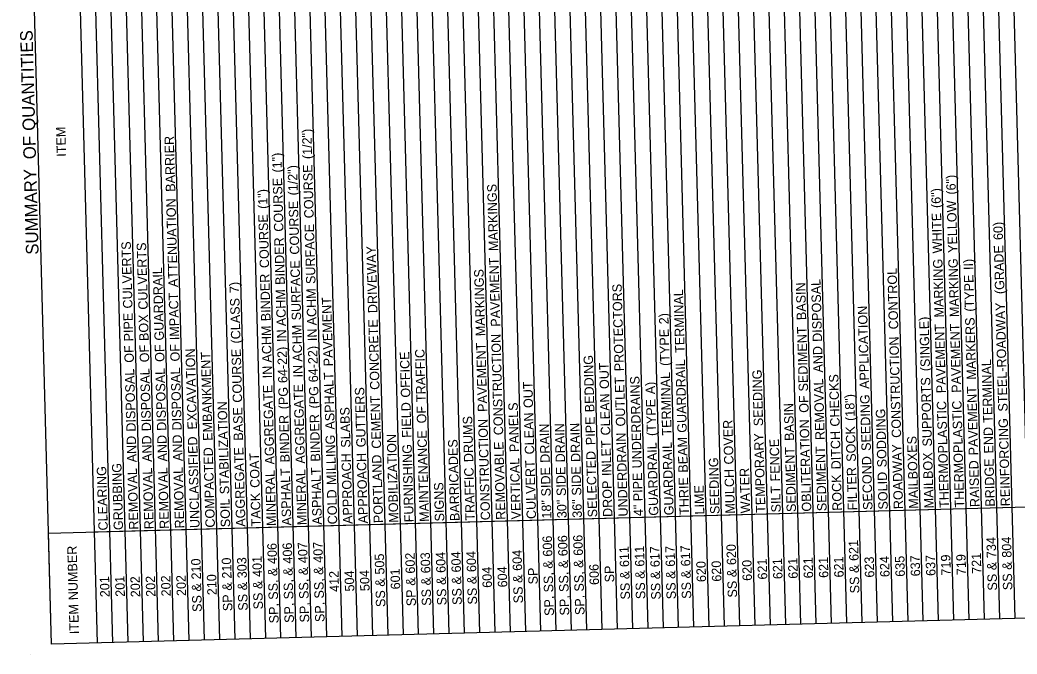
# Model space of a CAD drawing. Extents: x 1930078 to 1931323, y 596452 to 607874.
# Drawn here: x 1930078 to 1930714, y 606741 to 607145 of the extents above; entities that cross this region are included whole.
import ezdxf

# ---------------------------------------------------------------- set-up
doc = ezdxf.new("R2010")
doc.units = 0
doc.layers.add('Default', color=7, linetype='Continuous')
doc.layers.add('R_Border', color=7, linetype='Continuous')

msp = doc.modelspace()

# ---------------------------------------------------------------- linework, layer by layer
at = {"layer": 'Default'}
for p, q in [((1930546.92, 606759), (1930528.96, 607428.09)), ((1930556.67, 606759.26), (1930538.71, 607428.36)), ((1930566.41, 606759.52), (1930548.45, 607428.62)), ((1930576.16, 606759.78), (1930558.2, 607428.88)), ((1930585.91, 606760.04), (1930567.94, 607429.14)), ((1930595.65, 606760.31), (1930577.69, 607429.4)), ((1930605.4, 606760.57), (1930587.44, 607429.66)), ((1930615.15, 606760.83), (1930597.18, 607429.93)), ((1930624.89, 606761.09), (1930606.93, 607430.19)), ((1930634.64, 606761.35), (1930616.68, 607430.45)), ((1930644.38, 606761.61), (1930626.42, 607430.71)), ((1930654.13, 606761.88), (1930636.17, 607430.97)), ((1930663.88, 606762.14), (1930645.92, 607431.23)), ((1930673.62, 606762.4), (1930655.66, 607431.5)), ((1930683.37, 606762.66), (1930665.41, 607431.76)), ((1930693.12, 606762.92), (1930675.16, 607432.02)), ((1930702.86, 606763.18), (1930684.9, 607432.28)), ((1930712.61, 606763.45), (1930694.65, 607432.54)), ((1930722.36, 606763.71), (1930704.4, 607432.8)), ((1930313, 606752.72), (1930295.04, 607421.81)), ((1930322.75, 606752.98), (1930304.79, 607422.08)), ((1930332.5, 606753.24), (1930314.54, 607422.34)), ((1930342.24, 606753.5), (1930324.28, 607422.6)), ((1930351.99, 606753.76), (1930334.03, 607422.86)), ((1930361.74, 606754.03), (1930343.78, 607423.12)), ((1930371.48, 606754.29), (1930353.52, 607423.38)), ((1930381.23, 606754.55), (1930363.27, 607423.65)), ((1930390.98, 606754.81), (1930373.01, 607423.91)), ((1930400.72, 606755.07), (1930382.76, 607424.17)), ((1930410.47, 606755.33), (1930392.51, 607424.43)), ((1930420.22, 606755.6), (1930402.25, 607424.69)), ((1930429.96, 606755.86), (1930412, 607424.95)), ((1930439.71, 606756.12), (1930421.75, 607425.22)), ((1930449.46, 606756.38), (1930431.49, 607425.48)), ((1930459.2, 606756.64), (1930441.24, 607425.74)), ((1930468.95, 606756.9), (1930450.99, 607426)), ((1930478.69, 606757.17), (1930460.73, 607426.26)), ((1930488.44, 606757.43), (1930470.48, 607426.52)), ((1930498.19, 606757.69), (1930480.23, 607426.79)), ((1930507.93, 606757.95), (1930489.97, 607427.05)), ((1930517.68, 606758.21), (1930499.72, 607427.31)), ((1930527.43, 606758.47), (1930509.47, 607427.57)), ((1930537.17, 606758.74), (1930519.21, 607427.83)), ((1930098.58, 606746.96), (1930080.62, 607416.06)), ((1930127.82, 606747.75), (1930109.86, 607416.84)), ((1930137.57, 606748.01), (1930119.61, 607417.11)), ((1930147.31, 606748.27), (1930129.35, 607417.37)), ((1930157.06, 606748.53), (1930139.1, 607417.63)), ((1930166.81, 606748.79), (1930148.85, 607417.89)), ((1930176.55, 606749.06), (1930158.59, 607418.15)), ((1930186.3, 606749.32), (1930168.34, 607418.41)), ((1930196.05, 606749.58), (1930178.09, 607418.68)), ((1930205.79, 606749.84), (1930187.83, 607418.94)), ((1930215.54, 606750.1), (1930197.58, 607419.2)), ((1930225.29, 606750.36), (1930207.32, 607419.46)), ((1930235.03, 606750.63), (1930217.07, 607419.72)), ((1930244.78, 606750.89), (1930226.82, 607419.98)), ((1930254.53, 606751.15), (1930236.56, 607420.24)), ((1930264.27, 606751.41), (1930246.31, 607420.51)), ((1930274.02, 606751.67), (1930256.06, 607420.77)), ((1930283.76, 606751.93), (1930265.8, 607421.03)), ((1930293.51, 606752.19), (1930275.55, 607421.29)), ((1930303.26, 606752.46), (1930285.3, 607421.55)), ((1930720.46, 606834.37), (1930096.68, 606817.62)), ((1930720.46, 606834.37), (1930125.92, 606818.41)), ((1930098.58, 606746.96), (1930096.68, 606817.62)), ((1930898.77, 606768.44), (1930098.58, 606746.96)), ((1930898.77, 606768.44), (1930098.58, 606746.96))]:
    msp.add_line(p, q, dxfattribs=at)
at = {"layer": 'R_Border'}
msp.add_line((1930085.09, 606740.75), (1930085.09, 606740.75), dxfattribs=at)

# ---------------------------------------------------------------- texts
at = {"layer": 'Default'}
for s, height, p in [(' QUANTITIES', 8, (1930088.27, 607071.46)), ('ITEM', 6, (1930107.87, 607057.9)), (' (1/2")', 6, (1930264.7, 607054.18)), (' OF', 8, (1930088.76, 607053.36)), (' BARRIER', 6, (1930177.48, 607033.31)), (' (1")', 6, (1930245.42, 607045.61)), (' SUMMARY', 8, (1930090.39, 606992.5)), (' (1/2")', 6, (1930255.57, 607031.01)), (' COURSE', 6, (1930265.71, 607016.44)), (' COURSE', 6, (1930246.43, 607007.87)), (' (6")', 6, (1930674.95, 607031.52)), (' (1")', 6, (1930236.29, 607022.43)), (' MARKINGS', 6, (1930383.31, 606995.55)), (' (6")', 6, (1930665.43, 607022.98)), (' ATTENUATION', 6, (1930179.11, 606972.54)), (' COURSE', 6, (1930256.58, 606993.27)), (' YELLOW', 6, (1930675.95, 606994.36)), (' WHITE', 6, (1930666.2, 606994.1)), (' COURSE', 6, (1930237.3, 606984.69)), (' 60)', 6, (1930704.99, 607002.57)), (' SURFACE', 6, (1930266.84, 606974.51)), (' CULVERTS', 6, (1930150.21, 606958.91)), (' CULVERTS', 6, (1930159.99, 606958.17)), (' BINDER', 6, (1930247.34, 606973.99)), (' DRIVEWAY', 6, (1930306.35, 606955.97)), (' (GRADE', 6, (1930705.92, 606968.1)), (' SURFACE', 6, (1930257.7, 606951.34)), (' PAVEMENT', 6, (1930384.61, 606947.29)), (' MARKING', 6, (1930667.3, 606953.18)), (' MARKING', 6, (1930677.05, 606953.44)), (' II)', 6, (1930686, 606983.45)), (' GUARDRAIL', 6, (1930170.27, 606938.45)), (' MARKINGS', 6, (1930375.02, 606941.25)), (' CONTROL', 6, (1930638.25, 606945.61)), (' 7)', 6, (1930218.22, 606968.76)), (' BINDER', 6, (1930238.21, 606950.81)), (' BASIN', 6, (1930579.57, 606951.48)), (' DISPOSAL', 6, (1930589.69, 606937.64)), (' (TYPE', 6, (1930686.71, 606956.89)), (' IMPACT', 6, (1930180.02, 606938.72)), (' ACHM', 6, (1930248.05, 606947.61)), (' ACHM', 6, (1930267.54, 606948.14)), (' PROTECTORS', 6, (1930463.4, 606918.92)), (' TERMINAL', 6, (1930502.1, 606930.63)), (' (CLASS', 6, (1930219.09, 606936.59)), (' PAVEMENT', 6, (1930278, 606922.05)), (' STEEL-ROADWAY', 6, (1930707.93, 606893.19)), (' PIPE', 6, (1930150.78, 606937.93)), (' APPLICATION', 6, (1930619.76, 606907.63)), (' BOX', 6, (1930160.52, 606938.19)), (' CONCRETE', 6, (1930307.66, 606907.06)), (' 2)', 6, (1930491.86, 606948.86)), (' (SINGLE)', 6, (1930658.47, 606918.94)), (' MARKERS', 6, (1930687.87, 606913.55)), (' ACHM', 6, (1930238.92, 606924.44)), (' IN', 6, (1930248.32, 606937.59)), (' ACHM', 6, (1930258.41, 606924.96)), (' IN', 6, (1930267.81, 606938.12)), (' (TYPE', 6, (1930492.57, 606922.3)), (' SEDIMENT', 6, (1930580.79, 606906.01)), (' PAVEMENT', 6, (1930668.6, 606904.92)), (' PAVEMENT', 6, (1930678.34, 606905.18)), (' PAVEMENT', 6, (1930376.31, 606892.98)), (' CONSTRUCTION', 6, (1930386.47, 606878.13)), (' CONSTRUCTION', 6, (1930640.1, 606876.46)), (' OF', 6, (1930151.14, 606924.35)), (' OF', 6, (1930160.89, 606924.61)), (' OF', 6, (1930170.63, 606924.87)), (' OF', 6, (1930180.38, 606925.13)), (' EXCAVATION', 6, (1930191.3, 606881.74)), (' EMBANKMENT', 6, (1930201.24, 606874.55)), (' COURSE', 6, (1930220.1, 606898.86)), (' 64-22)', 6, (1930249.02, 606911.36)), (' 64-22)', 6, (1930268.52, 606911.88)), (' OFFICE', 6, (1930327.3, 606902.1)), (' TRAFFIC', 6, (1930337.13, 606899.24)), (' AND', 6, (1930590.22, 606918.06)), (' BEDDING', 6, (1930444.59, 606892.76)), (' OUT', 6, (1930453.95, 606907.59)), (' GUARDRAIL', 6, (1930503.47, 606879.7)), (' TERMINAL', 6, (1930698.37, 606886.05)), (' DISPOSAL', 6, (1930152.32, 606880.4)), (' DISPOSAL', 6, (1930162.07, 606880.66)), (' DISPOSAL', 6, (1930171.81, 606880.92)), (' DISPOSAL', 6, (1930181.56, 606881.18)), (' IN', 6, (1930239.19, 606914.42)), (' IN', 6, (1930258.68, 606914.94)), (' ASPHALT', 6, (1930279.08, 606881.7)), (' TERMINAL', 6, (1930493.76, 606877.89)), (' SEEDING', 6, (1930552.12, 606883.89)), (' OUT', 6, (1930405.51, 606895.48)), (' OUTLET', 6, (1930464.34, 606883.7)), (' UNDERDRAINS', 6, (1930474.81, 606856.99)), (' A)', 6, (1930483.3, 606904.19)), (' REMOVAL', 6, (1930591.37, 606875.05)), (' CHECKS', 6, (1930600.9, 606883.62)), (' SUPPORTS', 6, (1930659.76, 606870.94)), (' AGGREGATE', 6, (1930240.66, 606859.45)), (' (PG', 6, (1930249.47, 606894.66)), (' AGGREGATE', 6, (1930260.16, 606859.97)), (' (PG', 6, (1930268.97, 606895.18)), (' GUTTERS', 6, (1930298.89, 606870.43)), (' PAVEMENT', 6, (1930689.17, 606865.28)), (' STABILIZATION', 6, (1930211.91, 606840.5)), (' CEMENT', 6, (1930308.67, 606869.51)), (' FIELD', 6, (1930327.99, 606876.47)), (' PANELS', 6, (1930396.51, 606867.36)), (' CLEAN', 6, (1930454.74, 606878)), (' (TYPE', 6, (1930484.01, 606877.63)), (' OF', 6, (1930581.15, 606892.43)), (' (18")', 6, (1930610.55, 606887.25)), (' SEEDING', 6, (1930620.82, 606868.11)), ('THERMOPLASTIC', 6, (1930670.5, 606834)), ('THERMOPLASTIC', 6, (1930680.25, 606834.26)), (' BASE', 6, (1930220.75, 606874.61)), (' SLABS', 6, (1930289.14, 606870.16)), (' OF', 6, (1930337.5, 606885.66)), (' BASIN', 6, (1930571.88, 606874.52)), (' SODDING', 6, (1930630.85, 606857.66)), (' BINDER', 6, (1930250.38, 606860.78)), (' BINDER', 6, (1930269.87, 606861.3)), (' DRUMS', 6, (1930367.42, 606860.94)), ('CONSTRUCTION', 6, (1930378.11, 606826.15)), (' CLEAN', 6, (1930406.3, 606865.89)), (' PIPE', 6, (1930445.16, 606871.79)), (' COVER', 6, (1930533.27, 606859.46)), ('OBLITERATION', 6, (1930582.78, 606831.65)), ('REINFORCING', 6, (1930709.49, 606835.05)), ('MAINTENANCE', 6, (1930339.12, 606825.11)), (' DRAIN', 6, (1930416.2, 606860.54)), (' DRAIN', 6, (1930425.94, 606860.8)), (' DRAIN', 6, (1930435.69, 606861.06)), (' DITCH', 6, (1930601.63, 606856.37)), (' SOCK', 6, (1930611.25, 606861.19)), (' END', 6, (1930698.89, 606866.47)), (' AND', 6, (1930152.85, 606860.82)), (' AND', 6, (1930162.59, 606861.08)), (' AND', 6, (1930172.34, 606861.35)), (' AND', 6, (1930182.09, 606861.61)), ('UNCLASSIFIED', 6, (1930192.92, 606821.18)), (' MILLING', 6, (1930280.03, 606846.37)), ('MOBILIZATION', 6, (1930319.63, 606824.58)), ('BARRICADES', 6, (1930358.61, 606825.63)), ('REMOVABLE', 6, (1930387.85, 606826.42)), (' INLET', 6, (1930455.44, 606852.1)), ('UNDERDRAIN', 6, (1930465.83, 606828.51)), ('GUARDRAIL', 6, (1930485.32, 606829.03)), ('GUARDRAIL', 6, (1930495.06, 606829.29)), (' BEAM', 6, (1930504.15, 606854.25)), ('TEMPORARY', 6, (1930553.54, 606830.86)), (' FENCE', 6, (1930562.82, 606848.65)), ('MAILBOXES', 6, (1930651.01, 606833.48)), ('COMPACTED', 6, (1930202.67, 606821.44)), ('AGGREGATE', 6, (1930222.16, 606821.97)), ('FURNISHING', 6, (1930329.37, 606824.85)), ('SELECTED', 6, (1930446.33, 606827.99)), ('SEDIMENT', 6, (1930573.04, 606831.39)), ('SEDIMENT', 6, (1930592.53, 606831.91)), ('ROADWAY', 6, (1930641.26, 606833.22)), ('MAILBOX', 6, (1930660.76, 606833.74)), (' COAT', 6, (1930231.31, 606844.57)), ('APPROACH', 6, (1930290.39, 606823.8)), ('APPROACH', 6, (1930300.14, 606824.06)), ('PORTLAND', 6, (1930309.88, 606824.32)), ('VERTICAL', 6, (1930397.6, 606826.68)), ('CULVERT', 6, (1930407.35, 606826.94)), ('SEEDING', 6, (1930524.3, 606830.08)), ('SECOND', 6, (1930621.77, 606832.7)), ('RAISED', 6, (1930689.99, 606834.53)), ('BRIDGE', 6, (1930699.74, 606834.79)), ('CLEARING', 6, (1930134.44, 606819.61)), ('GRUBBING', 6, (1930144.19, 606819.87)), ('REMOVAL', 6, (1930153.94, 606820.14)), ('REMOVAL', 6, (1930163.68, 606820.4)), ('REMOVAL', 6, (1930173.43, 606820.66)), ('REMOVAL', 6, (1930183.18, 606820.92)), ('MINERAL', 6, (1930241.66, 606822.49)), ('ASPHALT', 6, (1930251.4, 606822.75)), ('MINERAL', 6, (1930261.15, 606823.01)), ('ASPHALT', 6, (1930270.9, 606823.28)), ('TRAFFIC', 6, (1930368.36, 606825.89)), (' SIDE', 6, (1930416.77, 606839.1)), (' SIDE', 6, (1930426.52, 606839.36)), (' SIDE', 6, (1930436.27, 606839.62)), (' PIPE', 6, (1930475.38, 606836.01)), ('MULCH', 6, (1930534.05, 606830.34)), ('WATER', 6, (1930543.8, 606830.6)), ('FILTER', 6, (1930612.02, 606832.43)), ('SOLID', 6, (1930631.52, 606832.96)), ('SIGNS', 6, (1930348.87, 606825.37)), ('DROP', 6, (1930456.08, 606828.25)), ('THRIE', 6, (1930504.81, 606829.56)), ('ROCK', 6, (1930602.28, 606832.17)), ('TACK', 6, (1930231.91, 606822.23)), ('COLD', 6, (1930280.64, 606823.54)), ('LIME', 6, (1930514.56, 606829.82)), ('SILT', 6, (1930563.29, 606831.13)), ('SOIL', 6, (1930212.42, 606821.71)), ('18"', 6, (1930417.09, 606827.2)), ('30"', 6, (1930426.84, 606827.46)), ('36"', 6, (1930436.59, 606827.72)), ('4"', 6, (1930475.57, 606828.77)), (' 407', 6, (1930271.61, 606796.8)), (' 606', 6, (1930417.8, 606800.72)), (' 606', 6, (1930427.55, 606800.99)), (' 606', 6, (1930437.3, 606801.25)), (' 621', 6, (1930612.95, 606797.98)), (' 734', 6, (1930700.68, 606799.77)), (' 804', 6, (1930710.43, 606800.03)), (' NUMBER', 6, (1930115.52, 606772.94)), (' 406', 6, (1930242.37, 606796.01)), (' 406', 6, (1930252.11, 606796.28)), (' 407', 6, (1930261.86, 606796.54)), (' 603', 6, (1930340.06, 606790.08)), (' 604', 6, (1930349.81, 606790.35)), (' 604', 6, (1930359.55, 606790.61)), (' 604', 6, (1930369.3, 606790.87)), (' 604', 6, (1930398.54, 606791.66)), (' 611', 6, (1930466.75, 606794.06)), (' 611', 6, (1930476.5, 606794.32)), (' 617', 6, (1930486.26, 606794)), (' 617', 6, (1930496.01, 606794.26)), (' 617', 6, (1930505.75, 606794.52)), (' 620', 6, (1930534.99, 606795.32)), (' 210', 6, (1930193.86, 606786.16)), (' 210', 6, (1930213.36, 606786.72)), (' 303', 6, (1930223.1, 606786.94)), (' 401', 6, (1930232.83, 606787.78)), (' 505', 6, (1930310.82, 606789.27)), (' 602', 6, (1930330.31, 606789.88)), (' &', 6, (1930418.01, 606793)), (' &', 6, (1930427.76, 606793.26)), (' &', 6, (1930437.5, 606793.52)), ('620', 6, (1930515.71, 606786.72)), ('620', 6, (1930525.46, 606786.99)), ('620', 6, (1930544.95, 606787.51)), ('621', 6, (1930554.69, 606788.34)), ('621', 6, (1930564.43, 606788.6)), ('621', 6, (1930574.18, 606788.86)), ('621', 6, (1930583.92, 606789.13)), ('621', 6, (1930593.67, 606789.39)), ('621', 6, (1930603.42, 606789.65)), ('623', 6, (1930622.93, 606789.59)), ('624', 6, (1930632.67, 606789.87)), ('635', 6, (1930642.42, 606790.09)), ('637', 6, (1930652.17, 606790.38)), ('637', 6, (1930661.91, 606790.64)), ('719', 6, (1930671.66, 606790.9)), ('719', 6, (1930681.41, 606791.16)), ('721', 6, (1930691.14, 606792)), (' &', 6, (1930700.89, 606792.04)), (' &', 6, (1930710.64, 606792.31)), (' &', 6, (1930242.57, 606788.29)), (' &', 6, (1930252.32, 606788.55)), (' &', 6, (1930262.07, 606788.81)), (' &', 6, (1930271.81, 606789.07)), ('412', 6, (1930281.8, 606780.47)), ('504', 6, (1930291.55, 606780.71)), ('504', 6, (1930301.29, 606780.97)), ('601', 6, (1930320.77, 606782.06)), ('604', 6, (1930379.26, 606783.06)), ('604', 6, (1930389.01, 606783.33)), ('SP', 6, (1930408.47, 606785.23)), (' SS,', 6, (1930428.16, 606778.17)), (' SS,', 6, (1930437.91, 606778.43)), ('606', 6, (1930447.49, 606784.88)), ('SP', 6, (1930457.2, 606786.53)), (' &', 6, (1930466.96, 606786.33)), (' &', 6, (1930476.7, 606786.59)), (' &', 6, (1930486.47, 606786.27)), (' &', 6, (1930496.21, 606786.54)), (' &', 6, (1930505.96, 606786.8)), (' &', 6, (1930535.2, 606787.59)), (' &', 6, (1930613.15, 606790.26)), ('201', 6, (1930135.59, 606777.09)), ('201', 6, (1930145.33, 606777.35)), ('202', 6, (1930155.09, 606777.07)), ('202', 6, (1930164.84, 606777.33)), ('202', 6, (1930174.59, 606777.59)), ('202', 6, (1930184.33, 606777.85)), ('210', 6, (1930203.83, 606778.35)), (' &', 6, (1930213.56, 606779)), (' &', 6, (1930223.31, 606779.21)), (' &', 6, (1930233.04, 606780.05)), (' SS,', 6, (1930242.98, 606773.2)), (' SS,', 6, (1930252.73, 606773.46)), (' SS,', 6, (1930262.47, 606773.72)), (' SS,', 6, (1930272.22, 606773.98)), (' &', 6, (1930311.03, 606781.54)), (' &', 6, (1930330.52, 606782.16)), (' &', 6, (1930340.27, 606782.35)), (' &', 6, (1930350.01, 606782.62)), (' &', 6, (1930359.76, 606782.89)), (' &', 6, (1930369.51, 606783.15)), (' &', 6, (1930398.75, 606783.93)), (' SS,', 6, (1930418.42, 606777.91)), ('SS', 6, (1930506.25, 606776.05)), ('SS', 6, (1930535.49, 606776.85)), ('SS', 6, (1930613.44, 606779.51)), ('SS', 6, (1930701.18, 606781.3)), ('SS', 6, (1930710.92, 606781.56)), (' &', 6, (1930194.07, 606778.44)), ('SS', 6, (1930311.32, 606770.8)), ('SP', 6, (1930330.81, 606771.34)), ('SS', 6, (1930340.56, 606771.61)), ('SS', 6, (1930350.3, 606771.88)), ('SS', 6, (1930360.05, 606772.14)), ('SS', 6, (1930369.8, 606772.4)), ('SS', 6, (1930399.04, 606773.19)), ('SS', 6, (1930467.25, 606775.59)), ('SS', 6, (1930476.99, 606775.85)), ('SS', 6, (1930486.75, 606775.53)), ('SS', 6, (1930496.5, 606775.79)), ('SS', 6, (1930194.36, 606767.69)), ('SP', 6, (1930213.85, 606768.18)), ('SS', 6, (1930223.6, 606768.47)), ('SS', 6, (1930233.33, 606769.31)), ('SP,', 6, (1930418.76, 606765.14)), ('SP,', 6, (1930428.51, 606765.41)), ('SP,', 6, (1930438.25, 606765.67)), ('ITEM', 6, (1930116.04, 606753.52)), ('SP,', 6, (1930243.32, 606760.43)), ('SP,', 6, (1930253.07, 606760.7)), ('SP,', 6, (1930262.82, 606760.96)), ('SP,', 6, (1930272.56, 606761.22))]:
    msp.add_text(s, height=height, rotation=91.53769, dxfattribs=at).set_placement(p)

doc.saveas('drawing.dxf')
